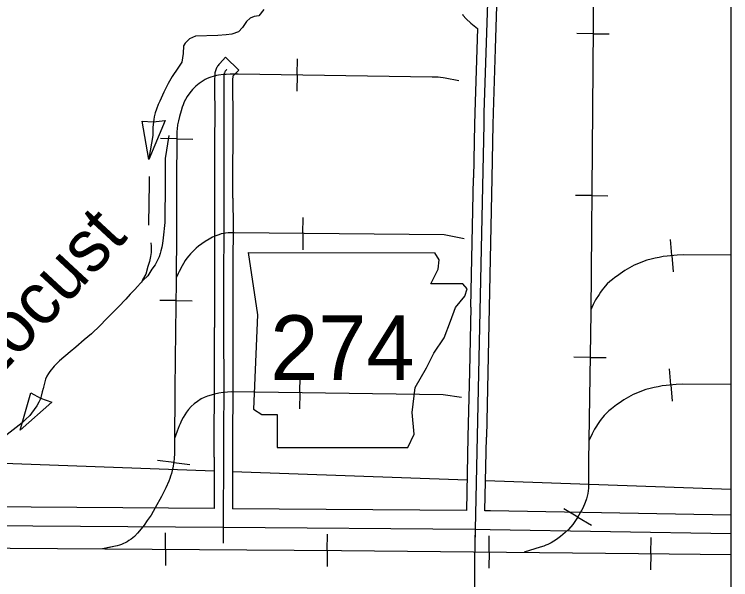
# Model space of a CAD drawing. Extents: x 1373094 to 1376427, y 1168361 to 1170494.
# Drawn here: x 1373883.2 to 1373980.6, y 1170067.3 to 1170144.1 of the extents above; entities that cross this region are included whole.
import ezdxf

# ---------------------------------------------------------------- set-up
doc = ezdxf.new("R2010")
doc.units = 0
doc.layers.add('R_Axis', color=7, linetype='Continuous')
doc.layers.add('R_No Plot', color=7, linetype='Continuous')

msp = doc.modelspace()

# ---------------------------------------------------------------- linework, layer by layer
at = {"layer": 'R_Axis'}
for p, q in [((1373961.887, 1170141.515), (1373959.687, 1170141.53)), ((1373961.887, 1170141.515), (1373964.087, 1170141.499)), ((1373921.651, 1170135.903), (1373921.686, 1170138.103)), ((1373921.651, 1170135.903), (1373921.617, 1170133.704)), ((1373901.485, 1170124.43), (1373900.569, 1170129.633)), ((1373900.569, 1170129.633), (1373902.079, 1170129.512)), ((1373903.708, 1170129.7), (1373901.485, 1170124.43)), ((1373902.079, 1170129.512), (1373903.708, 1170129.7)), ((1373905.266, 1170127.243), (1373903.067, 1170127.287)), ((1373905.266, 1170127.243), (1373907.466, 1170127.198)), ((1373961.707, 1170119.515), (1373959.507, 1170119.535)), ((1373961.707, 1170119.515), (1373963.907, 1170119.495)), ((1373922.429, 1170114.355), (1373922.451, 1170116.554)), ((1373922.429, 1170114.355), (1373922.407, 1170112.155)), ((1373972.599, 1170111.35), (1373972.408, 1170113.542)), ((1373914.996, 1170111.764), (1373916.265, 1170103.305)), ((1373940.937, 1170110.777), (1373940.353, 1170111.752)), ((1373972.599, 1170111.35), (1373972.79, 1170109.158)), ((1373940.796, 1170109.508), (1373940.937, 1170110.777)), ((1373939.809, 1170107.534), (1373940.796, 1170109.508)), ((1373944.18, 1170107.534), (1373939.809, 1170107.534)), ((1373944.744, 1170106.83), (1373944.18, 1170107.534)), ((1373944.462, 1170105.843), (1373944.744, 1170106.83)), ((1373905.149, 1170105.243), (1373902.949, 1170105.273)), ((1373905.149, 1170105.243), (1373907.349, 1170105.213)), ((1373943.193, 1170104.292), (1373944.462, 1170105.843)), ((1373942.488, 1170102.459), (1373943.193, 1170104.292)), ((1373916.265, 1170103.305), (1373915.701, 1170090.475)), ((1373941.642, 1170100.203), (1373942.488, 1170102.459)), ((1373940.232, 1170098.089), (1373941.642, 1170100.203)), ((1373939.245, 1170096.115), (1373940.232, 1170098.089)), ((1373961.478, 1170097.517), (1373959.279, 1170097.547)), ((1373961.478, 1170097.517), (1373963.678, 1170097.486)), ((1373937.695, 1170093.436), (1373939.245, 1170096.115)), ((1373972.467, 1170093.775), (1373972.276, 1170095.967)), ((1373922.009, 1170092.71), (1373922.04, 1170094.91)), ((1373937.272, 1170090.053), (1373937.695, 1170093.436)), ((1373972.467, 1170093.775), (1373972.658, 1170091.583)), ((1373883.982, 1170087.642), (1373885.419, 1170092.726)), ((1373885.419, 1170092.726), (1373886.726, 1170091.961)), ((1373922.009, 1170092.71), (1373921.979, 1170090.511)), ((1373888.275, 1170091.422), (1373883.982, 1170087.642)), ((1373886.726, 1170091.961), (1373888.275, 1170091.422)), ((1373915.701, 1170090.475), (1373916.829, 1170089.771)), ((1373916.829, 1170089.771), (1373918.944, 1170089.771)), ((1373918.944, 1170089.771), (1373918.944, 1170085.259)), ((1373937.554, 1170087.092), (1373937.272, 1170090.053)), ((1373936.708, 1170085.259), (1373937.554, 1170087.092)), ((1373918.944, 1170085.259), (1373936.708, 1170085.259)), ((1373904.858, 1170083.249), (1373902.673, 1170083.509)), ((1373904.858, 1170083.249), (1373907.042, 1170082.989)), ((1373959.792, 1170075.824), (1373957.894, 1170076.937)), ((1373959.792, 1170075.824), (1373961.689, 1170074.712)), ((1373903.742, 1170071.464), (1373903.757, 1170073.664)), ((1373925.742, 1170071.314), (1373925.757, 1170073.514)), ((1373947.741, 1170071.094), (1373947.763, 1170073.294)), ((1373969.739, 1170070.862), (1373969.767, 1170073.062)), ((1373903.742, 1170071.464), (1373903.727, 1170069.264)), ((1373925.742, 1170071.314), (1373925.727, 1170069.115)), ((1373947.741, 1170071.094), (1373947.718, 1170068.894)), ((1373969.739, 1170070.862), (1373969.712, 1170068.663))]:
    msp.add_line(p, q, dxfattribs=at)
for points in [[(1373974.278, 1170195.85), (1373973.59, 1170195.277), (1373973.02, 1170194.787), (1373972.036, 1170193.915), (1373971.174, 1170193.089), (1373970.132, 1170191.93), (1373969.014, 1170190.63), (1373968.233, 1170189.655), (1373967.667, 1170188.871), (1373967.16, 1170188.152), (1373966.321, 1170186.884), (1373965.853, 1170186.084), (1373965.267, 1170184.933), (1373964.584, 1170183.431), (1373963.78, 1170181.439), (1373963.199, 1170179.684), (1373962.786, 1170178.076), (1373962.536, 1170176.836), (1373962.383, 1170175.912), (1373962.199, 1170174.355), (1373962.106, 1170173.362), (1373961.98, 1170171.343), (1373962.054, 1170164.744), (1373961.814, 1170131.305)], [(1373962.054, 1170164.744), (1373961.814, 1170131.305), (1373961.562, 1170103.583)], [(1373947.917, 1170158.002), (1373947.048, 1170130.792)], [(1373948.856, 1170148.26), (1373948.575, 1170139.465)], [(1373917.125, 1170144.799), (1373916.41, 1170143.948), (1373915.814, 1170143.836), (1373915.268, 1170143.641), (1373914.763, 1170143.162), (1373914.197, 1170142.365), (1373913.661, 1170141.753), (1373912.768, 1170141.467), (1373911.972, 1170141.35), (1373910.842, 1170141.26), (1373907.821, 1170141.159)], [(1373944.105, 1170144.143), (1373944.186, 1170144.03), (1373944.641, 1170143.523), (1373945.253, 1170142.959), (1373946.162, 1170142.217)], [(1373946.162, 1170142.217), (1373945.798, 1170130.822), (1373945.797, 1170130.728)], [(1373907.821, 1170141.159), (1373907.014, 1170140.791), (1373906.393, 1170140.227), (1373906.185, 1170139.855), (1373906.14, 1170138.835), (1373905.982, 1170137.629), (1373905.417, 1170136.815), (1373904.658, 1170135.713), (1373904.096, 1170134.749), (1373903.505, 1170133.584), (1373902.949, 1170132.353), (1373902.74, 1170131.887), (1373902.505, 1170131.274), (1373902.342, 1170130.756), (1373902.211, 1170130.232), (1373902.137, 1170129.841), (1373902.094, 1170129.519), (1373902.026, 1170128.782), (1373902.014, 1170128.186), (1373901.999, 1170127.688)], [(1373948.575, 1170139.465), (1373948.297, 1170130.762), (1373948.296, 1170130.69)], [(1373911.918, 1170138.301), (1373911.125, 1170137.477), (1373911.077, 1170137.424), (1373911.032, 1170137.374), (1373910.979, 1170137.31), (1373910.895, 1170137.2), (1373910.816, 1170137.085), (1373910.745, 1170136.968), (1373910.682, 1170136.855), (1373910.615, 1170136.718), (1373910.567, 1170136.602), (1373910.526, 1170136.487), (1373910.483, 1170136.341), (1373910.457, 1170136.199), (1373910.439, 1170136.066), (1373910.434, 1170135.866), (1373910.419, 1170135.26), (1373910.43, 1170129.566), (1373910.426, 1170127.975)], [(1373913.719, 1170136.567), (1373911.918, 1170138.301)], [(1373912.072, 1170136.658), (1373912.036, 1170136.622), (1373912.005, 1170136.587), (1373911.98, 1170136.559), (1373911.956, 1170136.531), (1373911.907, 1170136.467), (1373911.868, 1170136.409), (1373911.826, 1170136.339), (1373911.79, 1170136.275), (1373911.756, 1170136.206), (1373911.733, 1170136.15), (1373911.714, 1170136.098), (1373911.701, 1170136.053), (1373911.692, 1170136.005), (1373911.687, 1170135.965), (1373911.683, 1170135.833), (1373911.669, 1170135.246), (1373911.68, 1170129.566)], [(1373912.926, 1170127.969), (1373912.93, 1170129.565), (1373912.919, 1170135.232), (1373912.932, 1170135.748), (1373912.933, 1170135.75), (1373912.948, 1170135.766), (1373913.719, 1170136.567)], [(1373943.609, 1170135.122), (1373941.787, 1170135.469), (1373941.483, 1170135.511), (1373941.124, 1170135.554), (1373940.82, 1170135.583), (1373940.469, 1170135.608), (1373939.987, 1170135.615), (1373913.618, 1170136.03), (1373912.539, 1170136.007), (1373912.004, 1170135.979), (1373911.619, 1170135.953), (1373910.945, 1170135.865), (1373910.682, 1170135.823), (1373910.379, 1170135.76), (1373909.75, 1170135.568), (1373909.418, 1170135.435), (1373909.112, 1170135.281), (1373908.853, 1170135.127), (1373908.31, 1170134.752), (1373908.083, 1170134.576), (1373907.868, 1170134.383), (1373907.712, 1170134.245), (1373907.404, 1170133.946), (1373907.042, 1170133.491), (1373906.708, 1170132.975), (1373906.471, 1170132.565), (1373906.299, 1170132.232), (1373906.126, 1170131.833), (1373906.008, 1170131.51), (1373905.863, 1170131.033), (1373905.653, 1170130.28), (1373905.498, 1170129.664), (1373905.395, 1170129.105), (1373905.321, 1170128.584), (1373905.294, 1170128.235), (1373905.27, 1170127.744), (1373905.27, 1170127.41), (1373905.265, 1170127.173), (1373905.259, 1170121.606), (1373905.216, 1170114.733), (1373905.186, 1170107.995), (1373905.094, 1170101.104), (1373904.989, 1170093.294), (1373904.982, 1170085.553), (1373904.981, 1170084.867), (1373904.943, 1170084.252), (1373904.936, 1170084.011), (1373904.909, 1170083.729), (1373904.872, 1170083.372), (1373904.833, 1170083.043), (1373904.794, 1170082.793), (1373904.73, 1170082.464), (1373904.661, 1170082.152), (1373904.552, 1170081.738), (1373904.443, 1170081.387), (1373904.325, 1170081.066), (1373904.18, 1170080.703), (1373903.767, 1170079.795), (1373903.175, 1170078.625), (1373902.35, 1170077.071), (1373901.776, 1170076.101), (1373901.263, 1170075.337), (1373900.85, 1170074.746), (1373900.438, 1170074.209), (1373899.952, 1170073.643), (1373899.516, 1170073.198), (1373899.3, 1170073.014), (1373899.075, 1170072.84), (1373898.777, 1170072.634), (1373898.513, 1170072.472), (1373898.266, 1170072.342), (1373898.03, 1170072.235), (1373897.755, 1170072.118), (1373897.493, 1170072.022), (1373897.149, 1170071.918), (1373896.707, 1170071.811), (1373895.331, 1170071.521)], [(1373939.987, 1170135.615), (1373913.618, 1170136.03), (1373912.539, 1170136.007), (1373912.004, 1170135.979), (1373911.619, 1170135.953), (1373910.945, 1170135.865), (1373910.682, 1170135.823), (1373910.379, 1170135.76), (1373909.75, 1170135.568), (1373909.418, 1170135.435), (1373909.112, 1170135.281), (1373908.853, 1170135.127), (1373908.31, 1170134.752), (1373908.083, 1170134.576), (1373907.868, 1170134.383), (1373907.712, 1170134.245), (1373907.404, 1170133.946), (1373907.042, 1170133.491), (1373906.708, 1170132.975), (1373906.471, 1170132.565), (1373906.299, 1170132.232), (1373906.126, 1170131.833), (1373906.008, 1170131.51)], [(1373943.609, 1170135.122), (1373941.787, 1170135.469), (1373941.483, 1170135.511), (1373941.124, 1170135.554), (1373940.82, 1170135.583), (1373940.469, 1170135.608), (1373939.987, 1170135.615)], [(1373906.008, 1170131.51), (1373905.863, 1170131.033), (1373905.653, 1170130.28), (1373905.498, 1170129.664), (1373905.395, 1170129.105), (1373905.321, 1170128.584), (1373905.294, 1170128.235), (1373905.27, 1170127.744), (1373905.27, 1170127.41), (1373905.265, 1170127.173), (1373905.259, 1170121.606), (1373905.216, 1170114.733), (1373905.186, 1170107.995), (1373905.094, 1170101.104), (1373904.989, 1170093.294), (1373904.982, 1170085.553), (1373904.981, 1170084.867), (1373904.943, 1170084.252), (1373904.936, 1170084.011), (1373904.909, 1170083.729), (1373904.872, 1170083.372), (1373904.833, 1170083.043), (1373904.794, 1170082.793), (1373904.73, 1170082.464), (1373904.661, 1170082.152), (1373904.552, 1170081.738), (1373904.443, 1170081.387), (1373904.325, 1170081.066), (1373904.18, 1170080.703), (1373903.767, 1170079.795), (1373903.175, 1170078.625), (1373902.35, 1170077.071), (1373901.776, 1170076.101), (1373901.263, 1170075.337), (1373900.85, 1170074.746), (1373900.438, 1170074.209), (1373899.952, 1170073.643), (1373899.516, 1170073.198), (1373899.3, 1170073.014), (1373899.075, 1170072.84), (1373898.777, 1170072.634), (1373898.513, 1170072.472), (1373898.266, 1170072.342), (1373898.03, 1170072.235), (1373897.755, 1170072.118), (1373897.493, 1170072.022), (1373897.149, 1170071.918), (1373896.707, 1170071.811), (1373896.269, 1170071.719), (1373895.188, 1170071.522)], [(1373961.814, 1170131.305), (1373961.562, 1170103.583), (1373961.324, 1170086.257), (1373961.272, 1170083.43), (1373961.258, 1170080.404), (1373961.24, 1170079.734), (1373961.218, 1170079.375), (1373961.158, 1170079.016), (1373961.088, 1170078.677), (1373960.983, 1170078.29), (1373960.81, 1170077.794), (1373960.476, 1170077.05), (1373960.131, 1170076.403), (1373959.764, 1170075.777), (1373959.408, 1170075.238), (1373959.106, 1170074.829), (1373958.524, 1170074.149), (1373958.082, 1170073.707), (1373957.775, 1170073.438), (1373957.438, 1170073.167), (1373956.928, 1170072.796), (1373956.567, 1170072.564), (1373956.162, 1170072.332), (1373955.731, 1170072.111), (1373955.456, 1170071.987), (1373955.17, 1170071.874), (1373954.674, 1170071.712), (1373952.507, 1170071.044)], [(1373945.797, 1170130.728), (1373945.774, 1170129.223), (1373945.619, 1170121.938)], [(1373947.048, 1170130.792), (1373947.023, 1170129.2), (1373945.809, 1170072.002)], [(1373948.296, 1170130.69), (1373948.273, 1170129.177), (1373948.118, 1170121.885)], [(1373911.68, 1170129.566), (1373911.662, 1170122.309), (1373911.674, 1170115.237), (1373911.64, 1170107.964), (1373911.636, 1170100.841), (1373911.665, 1170093.736), (1373911.605, 1170086.846), (1373911.588, 1170072.267)], [(1373904.19, 1170127.688), (1373903.674, 1170124.548), (1373903.714, 1170121.356), (1373903.64, 1170115.837), (1373903.437, 1170113.759), (1373903.337, 1170113.021), (1373903.249, 1170112.501), (1373903.127, 1170112.014), (1373903.036, 1170111.627), (1373902.879, 1170111.206), (1373902.656, 1170110.717), (1373902.32, 1170110.108), (1373901.9, 1170109.514), (1373901.32, 1170108.615), (1373900.701, 1170108), (1373899.579, 1170106.756), (1373898.927, 1170106.107), (1373898.341, 1170105.443), (1373897.348, 1170104.402), (1373896.467, 1170103.547), (1373895.686, 1170102.728), (1373894.871, 1170101.875), (1373893.68, 1170100.73), (1373892.683, 1170099.889), (1373891.554, 1170098.913), (1373890.786, 1170098.261), (1373889.329, 1170097.06), (1373888.595, 1170096.342), (1373888.011, 1170095.628), (1373887.835, 1170095.323), (1373887.626, 1170094.968), (1373887.435, 1170094.562), (1373887.19, 1170093.638), (1373887.114, 1170093.302), (1373886.991, 1170092.864), (1373886.821, 1170092.242), (1373886.729, 1170091.906), (1373886.523, 1170091.433), (1373886.234, 1170090.959), (1373885.879, 1170090.433), (1373885.523, 1170089.958), (1373885.297, 1170089.618), (1373884.692, 1170089.104), (1373884.236, 1170088.626), (1373879.14, 1170084.707)], [(1373901.999, 1170127.688), (1373901.483, 1170124.548), (1373901.485, 1170124.43)], [(1373910.426, 1170127.975), (1373910.412, 1170122.31), (1373910.417, 1170119.17)], [(1373912.917, 1170119.174), (1373912.912, 1170122.309), (1373912.926, 1170127.969)], [(1373901.512, 1170122.084), (1373901.523, 1170121.209), (1373901.449, 1170115.691), (1373901.429, 1170115.485)], [(1373945.432, 1170113.14), (1373945.619, 1170121.938)], [(1373948.118, 1170121.885), (1373947.932, 1170113.087)], [(1373910.417, 1170119.17), (1373910.424, 1170115.239), (1373910.401, 1170110.377)], [(1373912.917, 1170119.174), (1373912.924, 1170115.235), (1373912.901, 1170110.366)], [(1373944.375, 1170113.62), (1373941.628, 1170114.164), (1373913.076, 1170114.447), (1373912.275, 1170114.447), (1373911.901, 1170114.416), (1373911.61, 1170114.366), (1373911.328, 1170114.296), (1373910.995, 1170114.199), (1373910.584, 1170114.044), (1373910.139, 1170113.843), (1373909.684, 1170113.598), (1373909.136, 1170113.27), (1373908.698, 1170112.975), (1373908.234, 1170112.62), (1373907.89, 1170112.344), (1373907.643, 1170112.109), (1373907.408, 1170111.87), (1373907.13, 1170111.575), (1373906.902, 1170111.322), (1373906.658, 1170111.019), (1373906.43, 1170110.698), (1373906.168, 1170110.273), (1373906.011, 1170109.987), (1373905.609, 1170109.174), (1373905.482, 1170108.92), (1373905.188, 1170108.336)], [(1373944.375, 1170113.62), (1373941.628, 1170114.164), (1373913.076, 1170114.447), (1373912.275, 1170114.447), (1373911.901, 1170114.416), (1373911.61, 1170114.366), (1373911.328, 1170114.296), (1373910.995, 1170114.199), (1373910.584, 1170114.044), (1373910.139, 1170113.843), (1373909.684, 1170113.598), (1373909.136, 1170113.27), (1373908.698, 1170112.975), (1373908.234, 1170112.62), (1373907.89, 1170112.344), (1373907.643, 1170112.109), (1373907.408, 1170111.87), (1373907.13, 1170111.575), (1373906.902, 1170111.322), (1373906.658, 1170111.019), (1373906.43, 1170110.698), (1373906.168, 1170110.273), (1373906.011, 1170109.987), (1373905.609, 1170109.174), (1373905.482, 1170108.92), (1373905.188, 1170108.336)], [(1373901.75, 1170113.072), (1373901.773, 1170112.621), (1373901.8, 1170112.225), (1373901.773, 1170111.776), (1373901.704, 1170111.243), (1373901.562, 1170110.562), (1373901.335, 1170109.871), (1373901.044, 1170108.842), (1373900.633, 1170108.072), (1373900.466, 1170107.715)], [(1373945.246, 1170104.342), (1373945.432, 1170113.14)], [(1373947.932, 1170113.087), (1373947.745, 1170104.288)], [(1373914.996, 1170111.764), (1373940.353, 1170111.752)], [(1373980.591, 1170111.412), (1373974.204, 1170111.44), (1373973.319, 1170111.412), (1373971.952, 1170111.293), (1373971.397, 1170111.214), (1373970.862, 1170111.115), (1373970.317, 1170110.996), (1373969.762, 1170110.872), (1373969.207, 1170110.714), (1373968.613, 1170110.516), (1373968.068, 1170110.303), (1373967.478, 1170110.035), (1373966.844, 1170109.698), (1373966.196, 1170109.312), (1373965.561, 1170108.896), (1373965.18, 1170108.628), (1373964.828, 1170108.361), (1373964.506, 1170108.123), (1373964.165, 1170107.826), (1373963.818, 1170107.509), (1373963.521, 1170107.192), (1373963.332, 1170106.976), (1373963.109, 1170106.704), (1373962.887, 1170106.392), (1373962.688, 1170106.092), (1373962.223, 1170105.332), (1373961.902, 1170104.727), (1373961.565, 1170103.997)], [(1373980.591, 1170111.412), (1373974.204, 1170111.44), (1373973.319, 1170111.412), (1373971.952, 1170111.293), (1373971.397, 1170111.214), (1373970.862, 1170111.115), (1373970.317, 1170110.996), (1373969.762, 1170110.872), (1373969.207, 1170110.714), (1373968.613, 1170110.516), (1373968.068, 1170110.303), (1373967.478, 1170110.035), (1373966.844, 1170109.698), (1373966.196, 1170109.312), (1373965.561, 1170108.896), (1373965.18, 1170108.628), (1373964.828, 1170108.361), (1373964.506, 1170108.123), (1373964.165, 1170107.826), (1373963.818, 1170107.509), (1373963.521, 1170107.192), (1373963.332, 1170106.976), (1373963.109, 1170106.704), (1373962.887, 1170106.392), (1373962.688, 1170106.092), (1373962.223, 1170105.332), (1373961.902, 1170104.727), (1373961.565, 1170103.997)], [(1373910.401, 1170110.377), (1373910.39, 1170107.967), (1373910.386, 1170101.572)], [(1373912.901, 1170110.366), (1373912.89, 1170107.96), (1373912.886, 1170101.571)], [(1373898.927, 1170106.108), (1373898.927, 1170106.107), (1373898.341, 1170105.443), (1373897.348, 1170104.402), (1373896.467, 1170103.547), (1373895.686, 1170102.728), (1373894.871, 1170101.875), (1373894.341, 1170101.365)], [(1373945.246, 1170104.342), (1373945.059, 1170095.543)], [(1373947.745, 1170104.288), (1373947.558, 1170095.49)], [(1373961.562, 1170103.583), (1373961.324, 1170086.257), (1373961.272, 1170083.43), (1373961.258, 1170080.404), (1373961.24, 1170079.734), (1373961.218, 1170079.375), (1373961.158, 1170079.016), (1373961.088, 1170078.677), (1373960.983, 1170078.29), (1373960.81, 1170077.794), (1373960.476, 1170077.05), (1373960.131, 1170076.403), (1373959.764, 1170075.777), (1373959.408, 1170075.238), (1373959.106, 1170074.829), (1373958.524, 1170074.149), (1373958.082, 1170073.707), (1373957.775, 1170073.438), (1373957.438, 1170073.167), (1373956.928, 1170072.796), (1373956.567, 1170072.564), (1373956.162, 1170072.332), (1373955.731, 1170072.111), (1373955.456, 1170071.987), (1373955.17, 1170071.874), (1373954.674, 1170071.712), (1373952.507, 1170071.044)], [(1373910.406, 1170092.783), (1373910.415, 1170093.739), (1373910.386, 1170100.839), (1373910.386, 1170101.572)], [(1373912.886, 1170101.571), (1373912.886, 1170100.843), (1373912.915, 1170093.733), (1373912.906, 1170092.761)], [(1373892.698, 1170099.903), (1373892.683, 1170099.889), (1373891.554, 1170098.913), (1373890.786, 1170098.261), (1373889.329, 1170097.06), (1373888.595, 1170096.342), (1373888.011, 1170095.628), (1373887.89, 1170095.418)], [(1373945.059, 1170095.543), (1373944.872, 1170086.745)], [(1373947.558, 1170095.49), (1373947.372, 1170086.692)], [(1373887.13, 1170093.371), (1373887.114, 1170093.302), (1373886.991, 1170092.864), (1373886.821, 1170092.242), (1373886.729, 1170091.906), (1373886.523, 1170091.433), (1373886.234, 1170090.959), (1373885.879, 1170090.433), (1373885.523, 1170089.958), (1373885.297, 1170089.618), (1373884.692, 1170089.104), (1373884.27, 1170088.662)], [(1373980.591, 1170093.837), (1373974.072, 1170093.865), (1373973.187, 1170093.838), (1373971.82, 1170093.719), (1373971.265, 1170093.639), (1373970.73, 1170093.54), (1373970.185, 1170093.421), (1373969.63, 1170093.298), (1373969.075, 1170093.139), (1373968.481, 1170092.941), (1373967.936, 1170092.728), (1373967.347, 1170092.461), (1373966.712, 1170092.124), (1373966.064, 1170091.737), (1373965.43, 1170091.321), (1373965.048, 1170091.054), (1373964.374, 1170090.548), (1373964.033, 1170090.251), (1373963.686, 1170089.934), (1373963.389, 1170089.617), (1373963.2, 1170089.402), (1373962.978, 1170089.129), (1373962.755, 1170088.817), (1373962.091, 1170087.757), (1373961.77, 1170087.152), (1373961.323, 1170086.182)], [(1373980.591, 1170093.837), (1373974.072, 1170093.865), (1373973.187, 1170093.838), (1373971.82, 1170093.719), (1373971.265, 1170093.639), (1373970.73, 1170093.54), (1373970.185, 1170093.421), (1373969.63, 1170093.298), (1373969.075, 1170093.139), (1373968.481, 1170092.941), (1373967.936, 1170092.728), (1373967.347, 1170092.461), (1373966.712, 1170092.124), (1373966.064, 1170091.737), (1373965.43, 1170091.321), (1373965.048, 1170091.054), (1373964.374, 1170090.548), (1373964.033, 1170090.251), (1373963.686, 1170089.934), (1373963.389, 1170089.617), (1373963.2, 1170089.402), (1373962.978, 1170089.129), (1373962.755, 1170088.817), (1373962.091, 1170087.757), (1373961.77, 1170087.152), (1373961.323, 1170086.182)], [(1373943.983, 1170092.094), (1373941.507, 1170092.443), (1373912.702, 1170092.838), (1373912.166, 1170092.803), (1373911.602, 1170092.747), (1373910.983, 1170092.647), (1373910.414, 1170092.524), (1373909.957, 1170092.401), (1373909.466, 1170092.245), (1373909.02, 1170092.078), (1373908.606, 1170091.882), (1373908.1, 1170091.549), (1373907.659, 1170091.23), (1373907.228, 1170090.844), (1373906.879, 1170090.438), (1373906.615, 1170090.093), (1373906.377, 1170089.736), (1373906.146, 1170089.35), (1373905.931, 1170088.933), (1373905.719, 1170088.486), (1373905.607, 1170088.221), (1373905.474, 1170087.881), (1373905.328, 1170087.483), (1373904.983, 1170086.496)], [(1373943.983, 1170092.094), (1373941.507, 1170092.443), (1373912.702, 1170092.838), (1373912.166, 1170092.803), (1373911.602, 1170092.747), (1373910.983, 1170092.647), (1373910.414, 1170092.524), (1373909.957, 1170092.401), (1373909.466, 1170092.245), (1373909.02, 1170092.078), (1373908.606, 1170091.882), (1373908.1, 1170091.549), (1373907.659, 1170091.23), (1373907.228, 1170090.844), (1373906.879, 1170090.438), (1373906.615, 1170090.093), (1373906.377, 1170089.736), (1373906.146, 1170089.35), (1373905.931, 1170088.933), (1373905.719, 1170088.486), (1373905.607, 1170088.221), (1373905.474, 1170087.881), (1373905.328, 1170087.483), (1373904.983, 1170086.496)], [(1373910.352, 1170083.973), (1373910.355, 1170086.852), (1373910.406, 1170092.783)], [(1373912.906, 1170092.761), (1373912.855, 1170086.84), (1373912.852, 1170083.97)], [(1373944.872, 1170086.745), (1373944.659, 1170076.704)], [(1373947.159, 1170076.669), (1373947.372, 1170086.692)], [(1373853.731, 1170083.98), (1373859.299, 1170083.954), (1373910.35, 1170082.125)], [(1373910.352, 1170083.973), (1373910.344, 1170076.968)], [(1373912.852, 1170083.97), (1373912.844, 1170076.949)], [(1373912.85, 1170082.035), (1373944.748, 1170080.892)], [(1373947.247, 1170080.803), (1373980.591, 1170079.606)], [(1373802.085, 1170078.872), (1373802.872, 1170078.165), (1373803.761, 1170077.429), (1373804.507, 1170076.837), (1373805.393, 1170076.168), (1373805.835, 1170075.886), (1373806.285, 1170075.631), (1373807.322, 1170075.089), (1373808.487, 1170074.579), (1373810.183, 1170073.884), (1373811.901, 1170073.243), (1373812.657, 1170072.999), (1373813.616, 1170072.76), (1373814.679, 1170072.555), (1373816.068, 1170072.371), (1373817.421, 1170072.241), (1373821.537, 1170071.982), (1373823.468, 1170071.924), (1373832.053, 1170071.867), (1373848.16, 1170071.67), (1373876.12, 1170071.652), (1373927.651, 1170071.301), (1373968.061, 1170070.883), (1373980.591, 1170070.727)], [(1373910.344, 1170076.968), (1373879.208, 1170077.195), (1373869.135, 1170077.26)], [(1373944.659, 1170076.704), (1373912.844, 1170076.949)], [(1373980.591, 1170076.097), (1373947.934, 1170076.654), (1373947.159, 1170076.669)], [(1373869.119, 1170074.76), (1373879.191, 1170074.695), (1373911.595, 1170074.459), (1373945.821, 1170074.194), (1373947.889, 1170074.155), (1373980.591, 1170073.597)], [(1373945.823, 1170073.361), (1373945.043, 1169993.171), (1373944.352, 1169904.477), (1373944.122, 1169861.542)], [(1373848.16, 1170071.67), (1373876.12, 1170071.652), (1373927.651, 1170071.301), (1373968.061, 1170070.883), (1373980.591, 1170070.727)]]:
    msp.add_lwpolyline(points, dxfattribs=at)
at = {"layer": 'R_No Plot'}
msp.add_lwpolyline([(1373251.191, 1170420.714), (1373980.591, 1170420.714), (1373980.591, 1169636.224), (1373251.191, 1169636.224)], close=True, dxfattribs=at)

# ---------------------------------------------------------------- texts
at = {"layer": 'R_Axis'}
msp.add_text('Locust', height=7.04, rotation=47.19051, dxfattribs=at).set_placement((1373879.877, 1170093.433))
msp.add_text('274', height=8.8, dxfattribs=at).set_placement((1373917.983, 1170094.442))

doc.saveas('drawing.dxf')
